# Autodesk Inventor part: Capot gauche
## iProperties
Created: 2002-05
Part Number: Capot gauche
Material: Par défaut
Document SubType Name: Modélisation
Designer: Flavien MARTY
Control State: 0
Master: False
Checked Out: False
Shininess: 20.0
Length Units: 11269
Angle Units: 11279
Time Units: 11290
Mass Units: 11283
Length Display Precision: 3
Angle Display Precision: 2
Compacted: True
Density: 0.0
Volumn: 0.0
Area: 0.0
PropertySet Name: Model Information
Author: Flavien MARTY
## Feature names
1. Extrusion1
2. Extrusion2
3. Extrusion3
4. Chanfrein1 [Chamfer]
5. Extrusion4
6. Extrusion5
7. Extrusion6
8. Extrusion7
9. Extrusion8
10. Congé1 [Fillet]
11. Extrusion9
12. Extrusion10
13. Extrusion11
14. Extrusion12
15. Extrusion13
16. Congé2 [Fillet]
17. Extrusion14
18. Perçage1 [Hole]
19. Pion_femmelle [Extrusion]
20. Extrusion16
21. Extrusion17
22. Extrusion18
23. Perçage2 [Hole]
24. Extrusion19
25. Extrusion20
26. Extrusion21
27. Perçage3 [Hole]
28. Perçage4 [Hole]
29. Perçage5 [Hole]
30. Extrusion22
31. Perçage6 [Hole]
